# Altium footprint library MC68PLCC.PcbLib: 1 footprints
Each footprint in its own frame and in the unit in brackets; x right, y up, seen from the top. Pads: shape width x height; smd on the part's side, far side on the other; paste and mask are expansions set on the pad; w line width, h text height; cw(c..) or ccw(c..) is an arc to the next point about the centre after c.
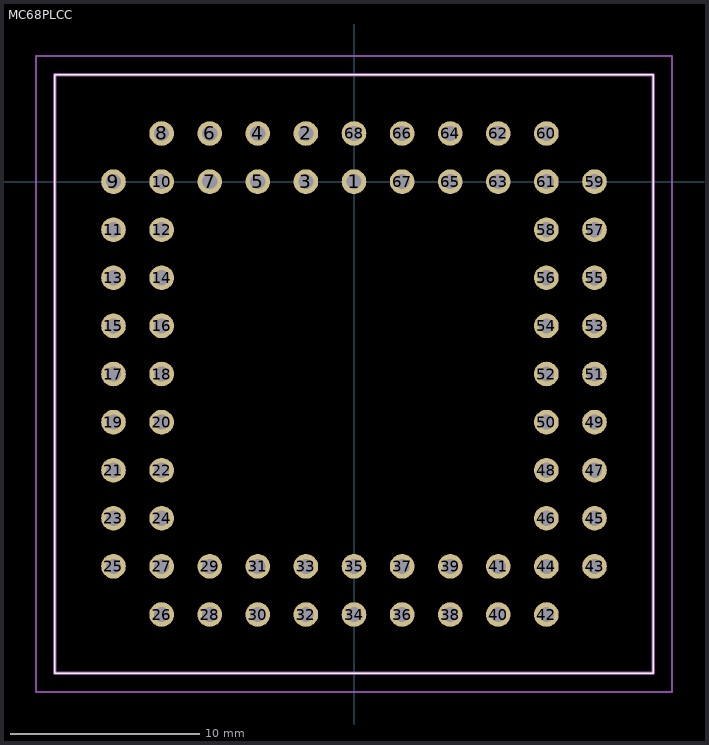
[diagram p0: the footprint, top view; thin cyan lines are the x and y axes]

## MC68PLCC [mm]
pads (68):
  round 1.3 hole 0.8: 1(0,0) 2(-2.54,2.54) 3(-2.54,0) 4(-5.08,2.54) 5(-5.08,0) 6(-7.62,2.54) 7(-7.62,0) 8(-10.16,2.54) 9(-12.7,0) 10(-10.16,0) 11(-12.7,-2.54) 12(-10.16,-2.54) 13(-12.7,-5.08) 14(-10.16,-5.08) 15(-12.7,-7.62) 16(-10.16,-7.62) 17(-12.7,-10.16) 18(-10.16,-10.16) 19(-12.7,-12.7) 20(-10.16,-12.7) 21(-12.7,-15.24) 22(-10.16,-15.24) 23(-12.7,-17.78) 24(-10.16,-17.78) 25(-12.7,-20.32) 26(-10.16,-22.86) 27(-10.16,-20.32) 28(-7.62,-22.86) 29(-7.62,-20.32) 30(-5.08,-22.86) 31(-5.08,-20.32) 32(-2.54,-22.86) 33(-2.54,-20.32) 34(0,-22.86) 35(0,-20.32) 36(2.54,-22.86) 37(2.54,-20.32) 38(5.08,-22.86) 39(5.08,-20.32) 40(7.62,-22.86) 41(7.62,-20.32) 42(10.16,-22.86) 43(12.7,-20.32) 44(10.16,-20.32) 45(12.7,-17.78) 46(10.16,-17.78) 47(12.7,-15.24) 48(10.16,-15.24) 49(12.7,-12.7) 50(10.16,-12.7) 51(12.7,-10.16) 52(10.16,-10.16) 53(12.7,-7.62) 54(10.16,-7.62) 55(12.7,-5.08) 56(10.16,-5.08) 57(12.7,-2.54) 58(10.16,-2.54) 59(12.7,0) 60(10.16,2.54) 61(10.16,0) 62(7.62,2.54) 63(7.62,0) 64(5.08,2.54) 65(5.08,0) 66(2.54,2.54) 67(2.54,0) 68(0,2.54)
Top Overlay:
  lines w0.1: -15.8,-25.96 15.8,-25.96 15.8,5.64 -15.8,5.64 -15.8,-25.96
Mechanical 15:
  lines w0.2: -15.8,-25.96 15.8,-25.96 15.8,5.64 -15.8,5.64 -15.8,-25.96
Mechanical 20:
  lines w0.1: -16.8,-26.96 16.8,-26.96 16.8,6.64 -16.8,6.64 -16.8,-26.96
3D body "MC-68PLCC.stp": height 5.8, standoff -4.65, extent -10,-3.376 10,3.376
